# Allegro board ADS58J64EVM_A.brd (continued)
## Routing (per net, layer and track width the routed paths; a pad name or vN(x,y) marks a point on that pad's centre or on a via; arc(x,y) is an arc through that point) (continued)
VCC1_VCC5_VCC6: length 6.6
  TOP w0.305: U5.10 87.77,63.51 v3(88.27,64.01) ; v3(82.55,52.96) 82.8,52.7 v3(83.54,52.7) v3(84.58,52.7) 84.77,52.89 U5.33 ; U5.36 86.27,53.11 ; 86.27,53.11 86.27,52.62 86.28,52.62 ; 86.27,53.11 v3(86.28,53.11) 86.28,52.62 ; 86.28,52.62 86.28,52.6 v3(86.49,52.4)
  vias: v3(77.34,51.94) v3(77.34,50.85) v3(78.36,51.94) v3(78.36,50.85) v3(79.38,51.94) v3(79.63,50.42) v3(80.19,51.41) v3(80.77,50.42) v3(81.15,51.94) v3(81.91,50.8) v3(83.57,51.69)
VCC2_CG1: length 0.6
  TOP w0.305: U5.17 v3(83.94,62.75)
  vias: v3(80.26,62.87) v3(81.15,62.87) v3(82.8,62.48) v3(83.31,62.99)
VCC3_SYSREF: length 5.4
  TOP w0.305: U5.21 v3(80.29,60.17)
  BOTTOM w0.254: C173.1 FB6.2
VCC4_CG2: length 7.3
  TOP w0.305: v3(78.49,57.53) v3(79.38,57.53) 79.51,57.67 v3(80.4,57.67) 80.41,57.66 v3(81.53,57.66) v3(83.06,57.66) 83.93,57.66 U5.26
  BOTTOM w0.254: C102.1 v3(79.38,57.53) v3(78.49,57.53)
VCC7_OSCOUT: length 3.2
  TOP w0.254: U5.39 v3(87.77,52.84)
  BOTTOM w0.254: v3(87.77,52.84) 87.77,51.57 87.76,51.56 FB3.2
VCC8_OSCIN: length 4.9
  TOP w0.305: U5.42 89.27,51.68 89.03,51.44 v3(89.03,50.93) v3(89.03,50.29)
  BOTTOM w0.254: FB11.2 89.28,50.67 v3(89.03,50.93)
VCC8_VCC10: length 3.9
  TOP w0.305: v3(94.67,52.17) v3(94.06,52.17) v3(93.45,52.17) 92.96,52.17 91.77,53.36 U5.47
  vias: v3(87.2,48.13) v3(87.2,47.19) v3(88.27,47.24) v3(88.29,48.16) v3(89.38,48.16) v3(89.41,47.17) v3(92.48,47.24) v3(93.09,48.06) v3(93.62,47.24) v3(96.01,52.45) v3(96.9,51.82) v3(97.79,52.45) v3(97.79,51.05) v3(99.82,51.82) v3(100.96,51.82) v3(102.11,52.32) v3(102.87,51.31)
VCC9_CP2: length 4.6
  TOP w0.305: U5.45 90.77,52.51 v3(90.8,52.48) 90.93,52.48 v3(91.41,51.99) v3(92.02,51.38) v3(92.58,50.83) v1(93.09,50.32)
  BOTTOM w0.254: C164.1 v3(90.8,52.48)
VCC11_CG3: length 0.9
  TOP w0.305: U5.53 v3(93.95,56.67)
  vias: v3(94.23,55.25) v3(95.05,56.39) v3(95.4,55.27) v3(96.65,55.25) v3(97.66,55.75) v3(98.93,56.26) v3(99.69,55.25)
VCC12_CG0: length 8.5
  TOP w0.305: C100.1 94.74,62.76 94.16,62.76 94.16,62.3 ; C100.1 94.84,62.3 ; C100.1 v3(94.82,62.66) ; U5.64 93.7,62.17 ; 93.7,62.17 93.7,62.3 94.16,62.3 ; 93.7,62.17 93.95,62.17 ; 94.16,62.3 93.95,62.3 93.95,62.17 ; 94.16,62.3 94.16,62.17 ; 94.16,62.3 94.16,62.4 94.48,62.3 94.84,62.3 ; 93.95,62.17 94.16,62.17 ; 94.16,62.17 94.33,62.17 ; 94.33,62.17 94.33,62.57 94.42,62.57 ; 94.33,62.17 95.05,62.17 95.05,62.3 ; 94.84,62.3 95.05,62.3 ; 95.05,62.3 95.18,62.3 v3(95.53,62.65) ; v3(94.82,62.66) 94.73,62.57 94.42,62.57 ; v3(94.82,62.66) 94.42,62.66 94.42,62.57
  TOP w0.508: C100.1 95.52,62.66 v3(95.53,62.65)
  vias: v3(93.37,62.28) v3(94.18,62.31)
AAINM: length 1.3
  TOP w0.508: T2.1 T1.3
AAINP: length 1.3
  TOP w0.508: T2.3 T1.1
ACLK_N: length 4.3
  TOP w0.241: C193.2 111.71,90.55 111.71,88.54 111.58,88.42 R34.2 111.58,88.11 111.7,88 111.7,86.92 111.64,86.86 U1.28
  vias: v1(111.61,90.68)
ACLK_P: length 4.3
  TOP w0.241: v1(112.22,90.68) 112.09,90.55 112.09,88.52 112.19,88.42 R34.1 112.19,88.11 112.08,88 112.08,86.92 112.14,86.86 U1.27
ACLKN: length 11.9
  BOTTOM w0.241: T5.3 111.46,101.85 111.72,101.59 111.72,91.86 111.61,91.74 R39.1
ACLKP: length 11.9
  BOTTOM w0.241: R35.1 112.22,91.74 112.1,91.86 112.1,101.64 112.32,101.85 T5.4
ADC_CLK: length 3.4
  BOTTOM w0.508: J6.1 C43.1
ADC_SCLK: length 90.2
  TOP w0.127: v1(47.88,55.63) 47.89,55.64 U3.33 ; v1(117.42,79.91) U1.6
  L6-PWR2 w0.127: v1(47.88,55.63) 47.98,55.52 50.24,55.52 50.44,55.73 58.27,55.73 J25.1 59.66,60.76 64.06,65.15 74.24,65.15 75.53,66.43 90.64,66.43 91.54,67.34 106.27,67.34 106.65,67.72 109.4,67.72 111.84,70.15 v1(113.28,70.15)
  BOTTOM w0.127: v1(117.42,79.91) 114.33,79.91 113.6,79.18 113.6,77.38 113.16,76.94 113.16,70.28 v1(113.28,70.15)
ADC_SDIO: length 101.3
  TOP w0.127: U3.35 46.89,54.46 v1(46.91,54.43) ; U1.5 118.45,79.41 119.02,78.83 v1(119.02,78.82)
  L6-PWR2 w0.127: v1(112.57,64.74) 102.34,64.74 101.78,64.19 91.82,64.19 91.05,63.41 76.77,63.41 76.26,63.92 75.04,63.92 74.63,63.5 64.82,63.5 62,60.68 62,53.09 60.96,52.04 J25.3 57.51,54.2 47.14,54.2 v1(46.91,54.43)
  BOTTOM w0.127: v1(112.57,64.74) 114.62,66.79 114.62,77.01 114.96,77.35 117.56,77.35 v1(119.02,78.82)
ADC_SDO: length 104.5
  TOP w0.127: U3.36 46.39,53.93 v1(46.3,53.85)
  L6-PWR2 w0.127: v1(46.3,53.85) 46.48,53.67 55.5,53.67 J25.4 61.11,49.5 62.99,51.38 62.99,60.3 64.49,61.8 84.51,61.8 84.96,62.26 92.18,62.26 92.81,61.62 95.43,61.62 96.42,62.61 105.13,62.61 106.68,64.16 109.09,64.16 109.78,63.47 v1(110.59,63.47)
  BOTTOM w0.127: v2(116.79,82.41) 115.96,82.41 112.66,79.11 112.64,68.5 112.17,68.02 112.17,66.24 111.25,65.33 111.25,64.14 v1(110.59,63.47)
ADC_SEN: length 98.4
  TOP w0.127: v1(118.72,80.04) 118.34,80.41 U1.7 ; U3.34 47.39,55.02 v1(47.42,54.99)
  L6-PWR2 w0.127: v1(113.41,67.03) 110.9,67.03 110.26,66.4 104.34,66.4 103.5,65.56 100.33,65.56 99.42,64.64 91.69,64.64 90.42,65.91 75.92,65.91 74.6,64.59 64.21,64.59 60.99,61.37 60.99,56.08 59.66,54.76 J25.2 59.56,54.69 47.73,54.69 v1(47.42,54.99)
  BOTTOM w0.127: v1(113.41,67.03) 114.21,67.83 114.21,77.05 114,77.27 114,79.09 114.41,79.5 118.19,79.5 v1(118.72,80.04)
ADCCLK: length 3.6
  BOTTOM w0.508: C43.2 111.89,104.9 112.39,104.39 T5.6
AIN+: length 16.5
  TOP w0.508: J1.1 76.8,93.85 76.8,87.33 arc(76.97,86.49) 77.44,85.78 arc(78.1,85.33) 78.89,85.18 T1.4
AINM: length 8.6
  TOP w0.241: R6.2 R63.1 100.14,83.85 106.46,83.85 106.52,83.91 U1.41
AINP: length 8.6
  TOP w0.241: R2.2 R101.2 100.14,83.47 106.47,83.47 106.53,83.41 U1.42
BBINM: length 1.3
  TOP w0.508: T7.1 T6.3
BBINP: length 1.3
  TOP w0.508: T7.3 T6.1
BIN: length 16.5
  TOP w0.508: T6.4 93.2,102.38 92.63,102.95 arc(92.36,103.35) 92.27,103.83 arc(92.34,104.21) 92.56,104.53 92.57,104.53 arc(93.03,104.84) 93.58,104.95 96,104.95 arc(96.87,105.31) 97.23,106.18 97.23,106.55 arc(96.87,107.41) 96.01,107.77 94.22,107.77 arc(93.93,107.83) 93.69,107.99 arc(93.4,108.42) 93.3,108.93 93.3,111.63 J17.1
BINM: length 8.6
  TOP w0.241: U1.37 106.99,86.23 102.38,90.84 R146.2 R142.2
BINP: length 8.7
  TOP w0.241: R141.2 R145.1 102.61,91.14 107.19,86.56 U1.36
CCINM: length 1.3
  TOP w0.508: T8.1 T9.3
CCINP: length 1.3
  TOP w0.508: T8.3 T9.1
CIN: length 16.5
  TOP w0.508: T8.4 134,101.76 arc(134.27,102.17) 134.37,102.65 134.37,102.65 arc(134.2,103.49) 133.72,104.21 arc(133.21,104.55) 132.6,104.67 130.23,104.67 arc(129.79,104.76) 129.42,105.01 arc(129.02,105.61) 128.88,106.32 arc(129.01,106.96) 129.37,107.5 129.63,107.76 arc(130.25,108.69) 130.47,109.78 J18.1
CINM: length 8.6
  TOP w0.241: U1.18 116.79,86.33 121.44,90.98 121.88,90.98 R157.1 R153.2
CINP: length 8.6
  TOP w0.241: R154.2 R158.2 121.03,91.11 116.48,86.56 U1.19
CLK_IN: length 5.8
  TOP w0.483: C122.1 v3(84.84,49.15)
  TOP w0.508: R62.2 v3(84.84,49.15)
CLK_LAO_0M: length 82.6
  TOP w0.241: C86.1 103.56,59 106.01,59 106.47,58.55 106.47,58.07 106.78,57.76 107.26,57.76 110.01,55.01 110.01,52.73 110.69,52.04 112.97,52.04 117.81,47.21 117.81,44.2 118.54,43.46 121.56,43.46 127.97,37.05 127.97,33.81 128.73,33.05 132.31,33.05 132.8,32.56 132.8,30.38 133.26,29.91 135.41,29.91 135.73,29.6 135.73,27.45 136.19,26.98 138.03,26.98 139.34,25.68 139.76,25.68 v3(140.06,25.39)
  BOTTOM w0.152: 155.89,20.83 155.89,20.79 155.96,20.73 155.96,16.54 155.8,16.38 J3.G7
  BOTTOM w0.241: v3(140.06,25.39) 140.35,25.68 151.98,25.68 152.46,25.2 152.46,24.63 152.69,24.4 153.26,24.4 155.89,21.77 155.89,20.83
CLK_LAO_0P: length 82.6
  TOP w0.241: C89.1 103.5,59.39 106.17,59.39 110.39,55.17 110.39,52.89 110.85,52.43 113.13,52.43 118.19,47.37 118.19,44.35 118.7,43.84 121.72,43.84 128.35,37.21 128.35,33.97 128.89,33.43 132.47,33.43 133.18,32.71 133.18,30.53 133.42,30.29 135.57,30.29 136.11,29.76 136.11,27.61 136.35,27.36 138.19,27.36 139.5,26.06 139.76,26.06 v3(140.06,26.35)
  BOTTOM w0.152: 156.27,20.83 156.27,20.79 156.21,20.73 156.21,16.54 156.36,16.38 156.72,16.38
  BOTTOM w0.241: v3(140.06,26.35) 140.35,26.06 152.14,26.06 156.27,21.93 156.27,20.83
CLK_N: length 6.8
  TOP w0.241: 84.35,64.32 84.39,64.32 84.77,63.95 U5.16
  TOP w0.254: 84.35,64.32 83.25,64.32 82.67,64.9 82.67,66.06 82.3,66.43 R40.1 82.25,66.98 82.25,67.51 82.3,67.56 C71.1
CLK_P: length 6.8
  TOP w0.241: U5.15 85.27,63.76 85.15,63.87 85.15,64.11 84.55,64.7 84.53,64.7 84.52,64.72 84.35,64.72
  TOP w0.254: 84.35,64.72 83.41,64.72 83.06,65.07 83.06,66.06 83.44,66.43 R21.1 C70.1
CLKIN: length 5.1
  TOP w0.508: R62.1 J12.1
CLKIN1N: length 3.8
  TOP w0.229: C175.2 C79.2
  TOP w0.241: C79.2 86.11,51.81 85.77,52.15 U5.35
CLKIN1P: length 2.7
  TOP w0.241: U5.34 85.27,52.24 84.84,51.81 C122.2
CLKLA_0N: length 13.4
  TOP w0.241: U5.63 93.97,61.67 94.02,61.61 94.65,61.61 95.19,61.08 95.19,60.04 95.76,59.46 96.6,59.46 97.01,59.87 97.01,60.72 97.47,61.19 98.99,61.19 99.46,60.72 99.46,59.6 99.7,59.36 100.74,59.36 R80.1 101.12,59.74 C89.2
CLKLA_0P: length 13.4
  TOP w0.241: C86.2 101.12,58.6 R79.1 100.74,58.98 99.54,58.98 99.08,59.44 99.08,60.57 98.84,60.81 97.63,60.81 97.39,60.57 97.39,59.71 96.76,59.08 95.61,59.08 94.81,59.88 94.81,60.92 94.5,61.23 94.02,61.23 93.97,61.17 U5.62
CLKM: length 52.1
  TOP w0.241: C48.2 111.61,91.74 111.72,91.86 111.72,93.33 110.53,94.52 110.23,94.52 110.14,94.43 109.84,94.43 109.63,94.64 109.63,94.94 109.72,95.03 109.72,95.33 109.35,95.71 108.62,95.71 v3(108.33,95.42)
  BOTTOM w0.241: v3(83.44,69.09) 83.06,69.47 83.06,82.21 83.47,82.63 84.05,82.63 84.27,82.85 84.27,83.43 96.58,95.73 97.15,95.73 97.48,95.4 97.87,95.4 98.2,95.73 108.01,95.73 v3(108.33,95.42)
CLKP: length 52.1
  TOP w0.241: v3(108.33,96.38) 108.62,96.09 109.5,96.09 112.1,93.49 112.1,91.86 112.22,91.74 C47.2
  BOTTOM w0.241: v3(82.3,69.09) 82.68,69.47 82.68,82.37 96.42,96.11 108.06,96.11 v3(108.33,96.38)
CP1: length 43.4
  TOP w0.254: v3(82.4,47.22) 82.4,52.12 81.28,53.24 C65.1 C60.1 81.74,54.61 81.79,54.67 U5.32
  BOTTOM w0.254: v3(82.4,47.22) 82.4,47.19 83.54,46.05 103.68,46.05 C94.2
  vias: v3(111.47,38.12)
CP2: length 5.3
  TOP w0.152: U5.46 91.27,53.13 93.09,51.31 C69.1 C66.1
DA_M: length 1.7
  TOP w0.241: C28.1 109.58,75.18 109.58,76.04 109.64,76.1 U1.59
DA_P: length 1.7
  TOP w0.241: U1.58 109.14,76.1 109.2,76.04 109.2,75.26 C27.1
DAM: length 87
  TOP w0.241: v1(150.37,8.76) 150.81,8.32 150.81,7.91 150.57,7.67 149.76,7.67 149.3,8.13 149.3,9.08 149.51,9.29 149.97,9.29 150.19,9.5 150.19,9.8 149.97,10.01 149.51,10.01 149.3,10.23 149.3,29.83 109.56,69.56 109.56,73.93 109.65,74.02 C28.2
DAP: length 87
  TOP w0.241: C27.2 109.04,74.07 109.18,73.93 109.18,69.41 148.92,29.67 148.92,7.98 149.61,7.29 150.73,7.29 151.19,7.75 151.19,8.32 v1(151.64,8.76)
DB_M: length 1.7
  TOP w0.241: U1.62 111.14,76.1 111.08,76.04 111.08,75.21 C30.1
DB_P: length 1.7
  TOP w0.241: U1.61 110.64,76.1 110.7,76.04 110.7,75.24 C29.1
DBM: length 88.8
  TOP w0.241: v1(155.45,8.76) 155.89,8.32 155.89,7.98 155.6,7.69 154.24,7.69 154.02,7.91 154.02,8.21 154.34,8.53 154.34,8.83 154.13,9.05 153.83,9.05 153.51,8.72 153.21,8.72 151.84,10.09 151.84,30.43 111.06,71.21 111.06,73.93 111.18,74.04 C30.2
DBP: length 88.7
  TOP w0.241: v1(156.72,8.76) 156.27,8.32 156.27,7.82 155.76,7.31 154.09,7.31 151.46,9.93 151.46,30.28 110.68,71.06 110.68,73.93 110.57,74.04 C29.2
DC_M: length 1.7
  TOP w0.241: C32.1 112.7,75.23 112.7,76.04 112.64,76.1 U1.65
DC_P: length 1.7
  TOP w0.241: U1.66 113.14,76.1 113.08,76.04 113.08,75.21 C31.1
DCM: length 89.2
  TOP w0.241: C32.2 112.57,74.04 112.69,73.93 112.69,71.92 154.05,30.56 154.05,11.07 155.27,9.86 160.73,9.86 160.97,9.61 160.97,9.21 v3(160.53,8.76)
DCP: length 89.2
  TOP w0.241: C31.2 113.18,74.04 113.07,73.93 113.07,72.08 154.43,30.71 154.43,11.23 155.43,10.24 160.89,10.24 161.35,9.77 161.35,9.21 v1(161.8,8.76)
DD_M: length 1.7
  TOP w0.241: C34.1 114.2,75.21 114.2,76.04 114.14,76.1 U1.68
DD_P: length 1.7
  TOP w0.241: C33.1 114.58,75.24 114.58,76.04 114.64,76.1 U1.69
DDINM: length 1.3
  TOP w0.508: T4.3 T3.1
DDINP: length 1.3
  TOP w0.508: T4.1 T3.3
DDM: length 81.2
  TOP w0.241: v3(155.45,11.3) 155.89,11.75 155.89,13.73 156.51,14.35 156.51,30.88 114.21,73.18 114.21,73.93 114.1,74.04 C34.2
DDP: length 81.2
  TOP w0.241: C33.2 114.71,74.04 114.59,73.93 114.59,73.34 156.9,31.04 156.9,14.19 156.27,13.57 156.27,11.75 v3(156.72,11.3)
DIN: length 16.5
  TOP w0.508: J5.1 146.98,89.77 arc(146.73,88.53) 146.03,87.48 141.55,83 arc(140.6,82.37) 139.47,82.14 T3.4
DINM: length 8.6
  TOP w0.241: U1.14 117.23,83.91 117.29,83.85 123.63,83.85 R119.2 R8.2
DINP: length 8.6
  TOP w0.241: R12.2 R107.1 123.63,83.47 117.3,83.47 117.24,83.41 U1.13
DRVDD1.15V: length 4.3
  TOP w0.241: v2(117.4,80.91) v2(116.79,80.91) ; v2(107.01,80.91) U1.47 106.74,80.91 106.2,80.37 v1(105.89,80.37)
  TOP w0.254: v1(117.98,80.92) 117.97,80.91 v2(117.4,80.91)
  BOTTOM w0.254: v1(117.98,80.92) 117.41,80.92 v2(117.4,80.91) v2(116.79,80.91) ; v2(106.39,80.55) 106.2,80.37 v1(105.89,80.37)
  vias: v1(40.01,85.52) v1(40.01,84.23) v1(40.11,88.62) v1(40.08,87.6) v1(40.08,86.64) v1(41.17,87.6) v1(41.17,86.64) v1(41.1,85.52) v1(41.1,84.23) v1(41.2,88.62) v1(42.37,88.6) v1(42.34,87.58) v1(42.34,86.61) v1(43.76,88.6) v1(43.74,87.58) v1(43.74,86.61) v1(44.3,85.39) v1(44.32,84.1) v1(45.16,88.62) v1(45.14,87.6) v1(45.14,86.64) v1(45.39,85.39) v1(45.42,84.1)
FMC_CLK_N: length 80.5
  BOTTOM w0.241: v1(110.97,90.68) 110.97,90.62 111.71,89.88 111.71,89.26 112.19,88.77 116.9,88.77 124.08,81.59 124.08,79.95 127.95,76.08 127.95,20.64 127.51,20.19
FMC_CLK_P: length 80.5
  BOTTOM w0.241: 128.78,20.19 128.33,20.64 128.33,76.24 124.46,80.11 124.46,81.75 117.06,89.15 112.35,89.15 112.09,89.41 112.09,89.86 112.85,90.62 v1(112.85,90.68)
FMC_D5: length 106.9
  TOP w0.127: U3.7 v1(54.4,47.47)
  L6-PWR2 w0.127: v1(54.4,47.47) 56.31,47.47 57.24,46.55 74.89,46.55 76.07,45.36 88.9,45.36 89.5,44.77 92.27,44.77 92.69,45.19 99.09,45.19 100.22,44.06 115.89,44.06 119.23,40.72 119.23,39.42 121.82,36.83 121.82,36.26 124.87,33.21 125.44,33.21 125.9,32.75 125.9,32.25 126.61,31.53 127.15,31.53 127.39,31.29 127.39,30.57 128.94,29.02 129.4,29.02 131.72,26.69 131.72,26.38 137.3,20.8 137.62,20.8 139.5,18.92 139.5,18.23 141.81,15.92 143.56,15.92 v1(144.02,16.38)
FMC_D6: length 106.7
  TOP w0.127: U3.8 v1(54.83,47.97)
  L6-PWR2 w0.127: v1(144.02,17.65) 144.02,17.55 143.52,17.05 141.47,17.05 140.32,18.19 140.32,18.59 136.77,22.14 136.77,23.07 136.27,23.57 135.99,23.57 127.72,31.84 126.91,31.84 126.2,32.55 126.2,32.96 125.64,33.52 125.33,33.52 125.08,33.76 125.08,34.3 123.42,35.97 123.26,35.97 119.76,39.46 119.76,41.03 118.52,42.27 118.52,42.97 117.04,44.44 116.64,44.44 115.24,45.85 76.4,45.85 75.11,47.14 57.49,47.14 56.67,47.97 v1(54.83,47.97)
FMC_DIR_CONTROL: length 105.5
  TOP w0.127: U3.15 v1(54.59,51.47)
  L6-PWR2 w0.127: v1(54.59,51.47) 54.78,51.47 58.52,47.73 75.26,47.73 76.66,46.33 116.2,46.33 120.76,41.77 120.76,40.64 120.65,40.52 120.65,39.99 125.06,35.58 125.06,35.13 128.71,31.48 129.46,31.48 129.71,31.24 129.71,30.7 v1(142.75,17.65)
FMC_SCLK: length 109.4
  TOP w0.127: U3.2 v1(54.98,44.97)
  L6-PWR2 w0.127: v1(54.98,44.97) 58.12,41.83 70.38,41.83 73,39.22 83.7,39.22 84.32,39.83 85.36,39.83 85.97,39.22 100.33,39.22 100.96,38.58 114.49,38.58 122.98,30.1 123.49,30.1 124,29.59 124,29.43 131.13,22.3 131.46,22.3 133.17,20.59 134.02,20.59 134.25,20.36 134.25,19.19 134.96,18.48 135.28,18.48 142.04,11.72 142.04,11.25 142.52,10.77 146.02,10.77 v1(146.56,11.3)
FMC_SDIO: length 107.4
  TOP w0.127: U3.3 v1(54.39,45.47)
  L6-PWR2 w0.127: v1(145.29,11.3) 145.12,11.47 143.15,11.47 134.92,19.69 134.92,20.12 133.8,21.25 133.37,21.25 130.67,23.95 130.1,23.95 126.56,27.49 126.56,27.72 123.75,30.53 123.33,30.53 122.28,31.59 122.28,32.11 118.08,36.31 117.5,36.31 114.09,39.73 91.64,39.73 88.48,42.89 85.41,42.89 84.96,42.44 58.22,42.44 55.19,45.47 v1(54.39,45.47)
FMC_SDO: length 108.9
  TOP w0.127: U3.4 v1(55.09,45.97)
  L6-PWR2 w0.127: v1(55.09,45.97) 55.42,45.97 58.47,42.93 84.68,42.93 85.09,43.33 88.72,43.33 89.38,42.67 94.26,42.67 95.55,41.38 113.79,41.38 120.82,34.35 121.38,34.35 121.63,34.11 121.63,33.61 125.3,29.93 125.68,29.93 125.92,29.69 125.92,29.3 126.87,28.35 127.23,28.35 129.65,25.92 129.65,25.91 132.88,22.69 132.88,22.66 133.3,22.24 133.34,22.24 137.36,18.21 137.67,18.21 138.15,17.73 138.15,17.25 143.36,12.04 145.97,12.04 146.51,12.57 v1(146.56,12.57)
FMC_SEN_ADC: length 107.9
  TOP w0.127: U3.5 v1(54.39,46.47)
  L6-PWR2 w0.127: v1(145.29,12.57) 144.89,12.97 143.07,12.97 140.59,15.45 140.59,15.77 133.82,22.54 133.43,22.54 133.18,22.79 133.18,23.18 130.49,25.87 130.49,26.26 130.25,26.5 129.71,26.5 127.11,29.1 126.83,29.1 126.58,29.34 126.58,29.78 125.66,30.7 125.3,30.7 125.06,30.94 125.06,31.51 123.47,33.1 122.86,33.1 122.17,33.79 122.17,34.19 121.45,34.91 121.01,34.91 113.99,41.94 95.76,41.94 94.54,43.15 89.48,43.15 88.7,43.94 83.11,43.94 82.85,43.69 58.43,43.69 55.65,46.47 v1(54.39,46.47)
FMC_SEN_LMK: length 106.8
  TOP w0.127: U3.6 v1(55.01,46.97)
  L6-PWR2 w0.127: v1(55.01,46.97) 56.03,46.97 56.98,46.02 74.55,46.02 76.16,44.41 77.18,44.41 77.74,44.97 88.47,44.97 89.65,43.79 94.79,43.79 96.06,42.52 114.78,42.52 122.95,34.35 122.95,33.76 123.19,33.52 123.79,33.52 129.01,28.29 129.4,28.29 131.3,26.4 131.3,25.79 133.71,23.38 133.78,23.38 134.02,23.14 134.02,23.06 141.57,15.52 144.42,15.52 v1(145.29,16.38)
FMC_SYSREF_N: length 80.5
  BOTTOM w0.241: 116.08,20.19 116.29,20.19 116.54,20.43 116.54,23.5 117.76,24.72 117.76,25.99 118.7,26.93 119.97,26.93 122.15,29.11 122.15,42.9 109.24,55.8 109.24,77.02 109.72,77.5 109.72,84.9 108.62,85.99 108.62,90.41 108.38,90.65 v1(107.87,90.65)
FMC_SYSREF_P: length 80.5
  BOTTOM w0.241: 117.35,20.19 117.12,20.19 116.92,20.4 116.92,23.34 118.14,24.56 118.14,25.83 118.86,26.55 120.13,26.55 122.53,28.95 122.53,43.05 109.62,55.96 109.62,76.86 110.1,77.35 110.1,85.05 109,86.15 109,90.41 109.25,90.65 v1(109.75,90.65)
FPGA_JESD_CLKM: length 82.6
  TOP w0.241: C67.2 104.01,62.48 105.86,62.48 140.79,27.56 141.38,27.56 141.38,27.55 v3(141.66,27.27)
  BOTTOM w0.152: 158.43,20.83 158.43,20.79 158.5,20.73 158.5,12.73 158.34,12.57 157.99,12.57
  BOTTOM w0.241: 158.43,20.83 158.13,21.13 158.13,21.47 158.43,21.77 158.43,22.16 154.27,26.31 153.62,26.31 153.32,26.61 153.32,26.96 153.32,26.97 153.32,27.27 153.03,27.56 141.95,27.56 v3(141.66,27.27)
FPGA_JESD_CLKP: length 82.6
  TOP w0.241: C68.2 104.01,62.87 106.02,62.87 140.94,27.94 141.38,27.94 141.38,27.95 v3(141.66,28.23)
  BOTTOM w0.152: 158.81,20.83 158.81,20.79 158.75,20.73 158.75,12.73 158.9,12.57 159.26,12.57
  BOTTOM w0.241: v3(141.66,28.23) 141.95,27.94 153.19,27.94 158.81,22.31 158.81,20.83
FPGA_JESD_SYSREFM: length 82.6
  TOP w0.241: 100.33,66.8 100.71,67.18 104.44,67.18 104.72,66.9 104.72,66.68 104.97,66.43 105.19,66.43 105.49,66.14 105.49,65.22 106.66,64.05 106.66,63.99 106.87,63.78 107.17,63.78 107.38,63.99 107.38,64.05 107.59,64.26 108.05,64.26 109.22,63.09 109.22,62.03 111.08,60.17 112.14,60.17 113.56,58.75 113.56,57.97 115.04,56.49 115.77,56.49 116.45,55.81 116.45,54.72 117.71,53.46 118.57,53.46 119.7,52.33 119.7,51.62 121.06,50.26 121.52,50.26 142.88,28.91 142.88,24.51 143.46,23.93 144.03,23.93 v3(144.35,23.61)
  BOTTOM w0.152: J3.G10 151.99,16.38 152.15,16.54 152.15,20.73 152.08,20.79 152.08,20.83
  BOTTOM w0.241: v3(144.35,23.61) 144.67,23.93 149.8,23.93 152.08,21.64 152.08,20.83
FPGA_JESD_SYSREFP: length 82.6
  TOP w0.241: 100.33,67.94 100.71,67.56 104.6,67.56 105.87,66.3 105.87,65.38 106.6,64.64 108.2,64.64 109.6,63.25 109.6,62.19 111.24,60.55 112.29,60.55 113.94,58.91 113.94,58.13 115.2,56.87 115.93,56.87 116.83,55.97 116.83,54.88 117.87,53.84 118.73,53.84 120.08,52.49 120.08,51.78 121.22,50.64 121.68,50.64 143.26,29.06 143.26,24.67 143.62,24.31 144.08,24.31 v3(144.35,24.57)
  BOTTOM w0.152: 152.46,20.83 152.46,20.79 152.4,20.73 152.4,16.54 152.55,16.38 J3.G9
  BOTTOM w0.241: v3(144.35,24.57) 144.61,24.31 149.95,24.31 152.46,21.8 152.46,20.83
FTDI_D5: length 12.1
  TOP w0.127: U3.54 35.72,54.97 v1(35.69,54.94)
  BOTTOM w0.127: U7.9 32.02,47.44 35.69,51.1 v1(35.69,54.94)
FTDI_D6: length 15.9
  TOP w0.127: v1(29.4,46.82) 29.18,47.04 29.18,50.55 34.11,55.47 U3.53
  BOTTOM w0.127: v1(29.4,46.82) 30.92,46.82 U7.10
FTDI_DIR_CONTROL: length 11.7
  TOP w0.127: v1(35.23,55.98) 37.68,55.98 U3.52
  BOTTOM w0.127: U7.6 32.52,49.39 35.23,52.1 v1(35.23,55.98)
FTDI_SCLK: length 7.2
  TOP w0.127: U3.61 33.32,51.47 v1(32.13,52.65)
  BOTTOM w0.127: v1(32.13,52.65) 32.11,52.64 U7.1
FTDI_SDIO: length 7.9
  TOP w0.127: U3.58 35.16,52.97 v1(34.82,52.63)
  BOTTOM w0.127: v1(34.82,52.63) 32.23,50.04 U7.5
FTDI_SDO: length 7.6
  TOP w0.127: U3.57 34.78,53.47 v1(33.93,52.63)
  BOTTOM w0.127: U7.3 32.67,51.34 33.8,52.47 v1(33.93,52.63)
FTDI_SEN_ADC: length 12
  TOP w0.127: U3.56 v1(36.25,53.97)
  BOTTOM w0.127: v1(36.25,53.97) 36.18,53.9 36.18,50.41 31.91,46.14 U7.11
FTDI_SEN_LMK: length 7.8
  TOP w0.127: U3.55 34.89,54.47 v1(33.05,52.63)
  BOTTOM w0.127: U7.2 32.4,51.99 v1(33.05,52.63)
IOVDD1.15V: length 7.8
  TOP w0.241: v2(112.14,76.76) 112.14,75.99 v1(111.86,75.72) ; v2(116.79,78.91) v2(117.24,78.91) 117.75,78.91 v1(117.75,78.92) ; v2(115.14,76.76) 115.14,75.9 v1(115.32,75.72) ; v1(106.07,78.89) 106.09,78.91 v2(106.99,78.91)
  TOP w0.254: v1(108.43,75.64) 108.64,75.84 v2(108.64,76.76)
  L3-PWR1 w0.127: 83.62,68.62 83.9,68.9 83.9,69.07
  BOTTOM w0.254: v2(116.79,78.91) v2(117.24,78.91) 117.25,78.92 v1(117.75,78.92) ; v1(106.07,78.89) 106.97,78.89 v2(106.99,78.91)
  vias: v2(108.64,76.19) v2(112.13,76.26) v2(115.13,76.28) v3(52.93,73.58) v3(52.93,72.52) v3(52.93,71.32) v3(52.93,70.18) v3(52.98,69.19) v3(54.08,73.63) v3(54.08,72.57) v3(54.08,71.37) v3(54.08,70.23) v3(54.13,69.24) v3(55.22,73.58) v3(55.22,72.52) v3(55.22,71.32) v3(55.22,70.18) v3(55.27,69.19) v3(56.26,73.61) v3(56.26,72.54) v3(56.26,71.35) v3(56.26,70.21) v3(56.31,69.22)
JESD_CLKM: length 13.4
  TOP w0.241: U5.2 91.77,63.87 91.83,63.93 91.83,64.39 92.31,64.87 95.31,64.87 95.89,64.29 99.55,64.29 100.95,62.89 102.26,62.89 v3(102.62,63.25)
JESD_CLKP: length 13.4
  TOP w0.241: U5.1 92.27,63.87 92.21,63.93 92.21,64.23 92.47,64.49 92.82,64.49 92.96,64.35 92.96,64.16 93.11,64.02 93.31,64.02 93.45,64.16 93.45,64.35 93.59,64.49 95.15,64.49 95.73,63.91 99.39,63.91 100.79,62.51 102.21,62.51 v3(102.62,62.1)
JESD_SYSREFM: length 13.3
  TOP w0.241: U5.4 90.77,63.87 90.83,63.93 90.83,66.75 91.95,67.87 94.06,67.87 94.57,67.36 95.31,67.36 95.77,67.82 97.23,67.82 97.43,67.61 98.98,67.61 v3(99.31,67.94)
JESD_SYSREFP: length 13.3
  TOP w0.241: v3(99.31,66.8) 98.88,67.23 97.27,67.23 97.07,67.44 95.93,67.44 95.47,66.98 94.41,66.98 93.9,67.49 93.24,67.49 93.1,67.35 93.1,67.17 92.96,67.03 92.76,67.03 92.62,67.17 92.62,67.35 92.47,67.49 92.11,67.49 91.21,66.59 91.21,63.93 91.27,63.87 U5.3
LMK_CS: length 66.8
  TOP w0.127: v3(62.38,61.82) 62.53,61.98 80.77,61.98 81.08,61.67 U5.18
  TOP w0.152: v3(61.9,40.94) 61.26,40.31 40.84,40.31 40.39,40.76 U3.78
  BOTTOM w0.127: v3(62.38,61.82) 62.38,41.43 v3(61.9,40.94)
LMK_SCK: length 68.1
  TOP w0.127: U5.19 81.02,61.17 80.54,61.65 77.52,61.65 77.18,61.31 63.38,61.31 v3(63.37,61.32)
  TOP w0.152: U3.77 39.89,40.37 40.61,39.65 62.23,39.65 v3(62.66,40.08)
  BOTTOM w0.127: v3(62.66,40.08) 63.14,40.56 63.14,61.09 v3(63.37,61.32)
LMK_SDIO: length 68.7
  TOP w0.127: U5.20 79.17,60.67 79.13,60.71 R134.2 76.23,60.71 76.2,60.67 64.3,60.67 v3(64.26,60.63)
  TOP w0.152: U3.76 39.39,39.86 40.23,39.01 63.02,39.01 v3(63.4,39.4)
  BOTTOM w0.127: v3(64.26,60.63) 63.98,60.35 63.96,60.32 63.96,39.95 v3(63.4,39.4)
LMK_SDO: length 65
  TOP w0.254: v3(90.17,64.52) 90.27,64.42 U5.5
  BOTTOM w0.127: v3(90.17,64.52) 89.71,64.52 89.46,64.26 88.77,64.26 88.16,64.87 64.34,64.87 61.54,62.08 61.54,49.48 60.43,48.36 53.65,48.36 50.75,45.47 R113.2
LMK_SYNC: length 22
  TOP w0.254: U5.6 89.77,63.9 89.28,64.39 v3(89.28,64.9)
  TOP w0.508: R59.1 72.9,68.12 J10.1
  BOTTOM w0.508: v3(72.95,68.15) 75.31,65.79 88.39,65.79 v3(89.28,64.9)
Net_375:
  vias: v1(155.45,20.19)
Net_376:
  vias: v1(157.99,20.19)
Net_377:
  vias: v1(113.54,20.19)
Net_379:
  vias: v1(119.89,20.19)
Net_380:
  vias: v1(121.16,20.19)
Net_381:
  vias: v1(123.7,20.19)
Net_382:
  vias: v1(124.97,20.19)
Net_383:
  vias: v1(131.32,20.19)
Net_384:
  vias: v1(132.59,20.19)
Net_389:
  vias: v1(142.75,20.19)
Net_390:
  vias: v1(144.02,20.19)
Net_391:
  vias: v1(146.56,20.19)
Net_393:
  vias: v1(150.37,20.19)
Net_395:
  vias: v1(163.07,20.19)
Net_396:
  vias: v1(152.91,18.92)
Net_397:
  vias: v1(155.45,18.92)
Net_399:
  vias: v1(114.81,18.92)
Net_400:
  vias: v1(117.35,18.92)
Net_401:
  vias: v1(118.62,18.92)
Net_402:
  vias: v1(121.16,18.92)
Net_403:
  vias: v1(122.43,18.92)
Net_404:
  vias: v1(124.97,18.92)
Net_405:
  vias: v1(126.24,18.92)
Net_406:
  vias: v1(160.53,18.92)
Net_407:
  vias: v1(128.78,18.92)
Net_408:
  vias: v1(130.05,18.92)
Net_409:
  vias: v1(132.59,18.92)
Net_410:
  vias: v1(133.86,18.92)
Net_413:
  vias: v1(161.8,18.92)
Net_416:
  vias: v1(144.02,18.92)
Net_417:
  vias: v1(145.29,18.92)
Net_422:
  vias: v1(155.45,17.65)
Net_423:
  vias: v1(157.99,17.65)
Net_424:
  vias: v1(113.54,17.65)
Net_425:
  vias: v1(159.26,17.65)
Net_426:
  vias: v1(116.08,17.65)
Net_427:
  vias: v1(117.35,17.65)
Net_428:
  vias: v1(119.89,17.65)
Net_429:
  vias: v1(121.16,17.65)
Net_430:
  vias: v1(127.51,17.65)
Net_431:
  vias: v1(128.78,17.65)
Net_432:
  vias: v1(131.32,17.65)
Net_433:
  vias: v1(132.59,17.65)
Net_434:
  vias: v1(135.13,17.65)
Net_438:
  vias: v1(146.56,17.65)
Net_440:
  vias: v1(150.37,17.65)
Net_442:
  vias: v1(163.07,17.65)
Net_443:
  vias: v1(114.81,16.38)
Net_444:
  vias: v1(117.35,16.38)
Net_445:
  vias: v1(118.62,16.38)
Net_446:
  vias: v1(121.16,16.38)
Net_447:
  vias: v1(122.43,16.38)
Net_448:
  vias: v1(124.97,16.38)
Net_449:
  vias: v1(126.24,16.38)
Net_450:
  vias: v1(160.53,16.38)
Net_451:
  vias: v1(128.78,16.38)
Net_452:
  vias: v1(130.05,16.38)
Net_453:
  vias: v1(132.59,16.38)
Net_454:
  vias: v1(133.86,16.38)
Net_455:
  vias: v1(136.4,16.38)
Net_457:
  vias: v1(161.8,16.38)
Net_461:
  vias: v1(155.45,15.11)
Net_462:
  vias: v1(157.99,15.11)
Net_463:
  vias: v1(113.54,15.11)
Net_464:
  vias: v1(159.26,15.11)
Net_465:
  vias: v1(116.08,15.11)
Net_466:
  vias: v1(117.35,15.11)
Net_467:
  vias: v1(119.89,15.11)
Net_468:
  vias: v1(121.16,15.11)
Net_469:
  vias: v1(123.7,15.11)
Net_470:
  vias: v1(124.97,15.11)
Net_471:
  vias: v1(127.51,15.11)
Net_472:
  vias: v1(128.78,15.11)
Net_473:
  vias: v1(131.32,15.11)
Net_474:
  vias: v1(132.59,15.11)
Net_475:
  vias: v1(135.13,15.11)
Net_476:
  vias: v1(136.4,15.11)
Net_479:
  vias: v1(142.75,15.11)
Net_480:
  vias: v1(144.02,15.11)
Net_481:
  vias: v1(146.56,15.11)
Net_482:
  vias: v1(147.83,15.11)
Net_483:
  vias: v1(150.37,15.11)
Net_485:
  vias: v1(163.07,15.11)
Net_489:
  vias: v1(114.81,13.84)
Net_490:
  vias: v1(117.35,13.84)
Net_491:
  vias: v1(118.62,13.84)
Net_492:
  vias: v1(121.16,13.84)
Net_493:
  vias: v1(122.43,13.84)
Net_494:
  vias: v1(124.97,13.84)
Net_495:
  vias: v1(126.24,13.84)
Net_496:
  vias: v1(160.53,13.84)
Net_497:
  vias: v1(128.78,13.84)
Net_498:
  vias: v1(130.05,13.84)
Net_499:
  vias: v1(132.59,13.84)
Net_500:
  vias: v1(133.86,13.84)
Net_501:
  vias: v1(136.4,13.84)
Net_502:
  vias: v1(137.67,13.84)
Net_503:
  vias: v1(161.8,13.84)
Net_506:
  vias: v1(144.02,13.84)
Net_507:
  vias: v1(145.29,13.84)
Net_508:
  vias: v1(147.83,13.84)
Net_511:
  vias: v1(152.91,12.57)
Net_513:
  vias: v1(113.54,12.57)
Net_514:
  vias: v1(116.08,12.57)
Net_515:
  vias: v1(118.62,12.57)
Net_516:
  vias: v1(119.89,12.57)
Net_517:
  vias: v1(121.16,12.57)
Net_518:
  vias: v1(122.43,12.57)
Net_519:
  vias: v1(123.7,12.57)
Net_520:
  vias: v1(124.97,12.57)
Net_521:
  vias: v1(126.24,12.57)
Net_522:
  vias: v1(127.51,12.57)
Net_523:
  vias: v1(130.05,12.57)
Net_524:
  vias: v1(131.32,12.57)
Net_525:
  vias: v1(133.86,12.57)
Net_526:
  vias: v1(135.13,12.57)
Net_527:
  vias: v1(137.67,12.57)
Net_528:
  vias: v1(138.94,12.57)
Net_532:
  vias: v1(150.37,12.57)
Net_533:
  vias: v1(163.07,12.57)
Net_534:
  vias: v1(114.81,11.3)
Net_535:
  vias: v1(117.35,11.3)
Net_536:
  vias: v1(119.89,11.3)
Net_537:
  vias: v1(121.16,11.3)
Net_538:
  vias: v1(124.97,11.3)
Net_539:
  vias: v1(126.24,11.3)
Net_540:
  vias: v1(160.53,11.3)
Net_541:
  vias: v1(130.05,11.3)
Net_542:
  vias: v1(131.32,11.3)
Net_543:
  vias: v1(135.13,11.3)
Net_544:
  vias: v1(136.4,11.3)
Net_545:
  vias: v1(161.8,11.3)
Net_546:
  vias: v1(140.21,11.3)
Net_549:
  vias: v1(152.91,10.03)
Net_550:
  vias: v1(154.18,10.03)
Net_552:
  vias: v1(113.54,10.03)
Net_554:
  vias: v1(117.35,10.03)
Net_555:
  vias: v1(118.62,10.03)
Net_556:
  vias: v1(122.43,10.03)
Net_557:
  vias: v1(123.7,10.03)
Net_558:
  vias: v1(127.51,10.03)
Net_559:
  vias: v1(128.78,10.03)
Net_560:
  vias: v1(132.59,10.03)
Net_561:
  vias: v1(133.86,10.03)
Net_562:
  vias: v1(137.67,10.03)
Net_563:
  vias: v1(138.94,10.03)
Net_568:
  vias: v1(163.07,10.03)
Net_569:
  vias: v1(114.81,8.76)
Net_570:
  vias: v1(116.08,8.76)
Net_571:
  vias: v1(119.89,8.76)
Net_572:
  vias: v1(121.16,8.76)
Net_573:
  vias: v1(124.97,8.76)
Net_574:
  vias: v1(126.24,8.76)
Net_575:
  vias: v1(130.05,8.76)
Net_576:
  vias: v1(131.32,8.76)
Net_577:
  vias: v1(135.13,8.76)
Net_578:
  vias: v1(136.4,8.76)
Net_579:
  vias: v1(140.21,8.76)
Net_580:
  vias: v1(141.48,8.76)
Net_581:
  vias: v1(145.29,8.76)
Net_582:
  vias: v1(146.56,8.76)
OSCIN_N: length 13.9
  TOP w0.241: U5.44 90.27,52.97 90.21,52.91 90.21,49.9 91.19,48.93 91.19,44.85 91.4,44.63 91.53,44.63 91.74,44.42 91.74,44.12 91.53,43.91 91.4,43.91 91.19,43.7 91.19,43.21 91.6,42.8 92.45,42.8 C82.2
OSCIN_P: length 13.9
  TOP w0.241: C121.2 92.43,42.42 91.44,42.42 90.8,43.05 90.8,48.77 89.83,49.74 89.83,52.91 89.77,52.97 U5.43
PDN: length 84.9
  TOP w0.127: v1(106.1,69.62) 105.51,70.21 101.55,70.21 99.59,72.16 99.59,77.83 101.18,79.41 U1.50
  L6-PWR2 w0.127: v1(106.1,69.62) 107.69,71.21 116.21,71.21 117.09,70.33 129.74,70.33 129.95,70.13 153.31,70.13 161.87,78.69 163.4,78.69 JP7.2
RESET: length 99.6
  TOP w0.127: U1.48 106.78,80.41 106.23,79.86 100.88,79.86 99.11,78.09 99.11,72.01 101.37,69.75 105.18,69.75 v1(106.12,68.81)
  L6-PWR2 w0.127: v1(167.69,66.9) 168.4,67.61 168.4,76.07 168.05,76.43 162,76.43 154.94,69.37 119.9,69.37 119.76,69.23 116.46,69.23 114.95,70.74 109.25,70.74 108.53,70.03 107.34,70.03 v1(106.12,68.81)
SCAN_EN: length 13
  BOTTOM w0.127: v2(106.99,79.91) 100.94,79.91 99.95,78.92 R19.2 R20.1 94.67,78.92 TP20.1
SYNCBABM: length 78.7
  TOP w0.241: U1.56 108.14,76.43 107.49,75.79 107.49,68.5 145.9,30.1 145.9,23.13 146.06,22.96 v3(146.25,22.96)
  BOTTOM w0.152: 148.27,20.83 148.27,20.79 148.34,20.73 148.34,16.54 148.18,16.38 J3.G13
  BOTTOM w0.241: 148.27,20.83 148.27,21.59 147.94,21.92 146.87,21.92 146.55,22.24 146.55,22.66 v3(146.25,22.96)
SYNCBABP: length 79.4
  TOP w0.241: U1.55 107.64,76.47 107.11,75.95 107.11,68.35 145.52,29.94 145.52,22.97 146.04,22.45 146.47,22.45 146.47,22.45 v3(147.07,22.45)
  BOTTOM w0.152: 149.1,16.38 148.74,16.38 148.59,16.54 148.59,20.73 148.65,20.79 148.65,20.83
  BOTTOM w0.241: v3(147.07,22.45) 147.22,22.3 148.1,22.3 148.65,21.75 148.65,20.83
SYNCBCDM: length 58.1
  BOTTOM w0.152: 124.16,20.69 124.21,20.65 124.21,17.81 124.05,17.65 123.7,17.65
  BOTTOM w0.241: v1(116.76,72.26) 116.76,71.76 116.88,71.65 116.88,70.57 124.16,63.29 124.16,20.69
SYNCBCDP: length 58.1
  BOTTOM w0.152: 124.54,20.85 124.46,20.77 124.46,17.81 124.61,17.65 J3.H31
  BOTTOM w0.241: 124.54,20.85 124.54,63.44 117.26,70.73 117.26,71.65 117.37,71.76 v1(117.37,72.26)
SYSREF+: length 4.3
  TOP w0.241: U1.33 109.14,86.8 109.07,86.87 109.07,87.6 R133.1 109.03,87.85 109.03,90.54 C190.2
SYSREF-: length 4.3
  TOP w0.241: R31.2 108.65,90.49 108.65,87.8 R133.2 108.69,87.58 108.69,86.82 108.64,86.77 U1.34
SYSREF_N: length 6.8
  TOP w0.254: U5.14 85.77,63.89 85.82,63.94 85.82,64.61 86.74,65.53 87.76,65.53 88.11,65.89 88.11,66.57 R44.1 C72.1
SYSREF_P: length 6.8
  TOP w0.254: U5.13 86.27,63.89 86.21,63.94 86.21,64.45 86.9,65.14 87.92,65.14 88.51,65.72 88.51,66.54 88.9,66.93 C73.1
SYSREFM: length 52.1
  TOP w0.241: R31.1 108.48,91.69 108.62,91.83 108.62,92.38 108.29,92.71 107.66,92.71 107.45,92.5 107.45,92.36 107.23,92.15 106.93,92.15 106.72,92.36 106.72,92.5 106.51,92.71 105.96,92.71 v3(105.71,92.47)
  BOTTOM w0.241: v3(105.71,92.47) 105.47,92.71 99.83,92.71 99.43,92.3 99.11,92.3 98.7,92.71 97.82,92.71 89.81,84.7 89.81,84.05 89.57,83.81 89.22,83.81 89.22,83.81 88.92,83.81 88.52,83.41 88.52,76.54 89,76.06 93.88,76.06 94.64,75.3 94.64,72.43 93.88,71.67 89,71.67 88.52,71.19 88.52,69.47 v3(88.9,69.09)
SYSREFP: length 52.1
  TOP w0.241: R30.1 109.14,91.69 109,91.83 109,92.54 108.45,93.09 106.06,93.09 v3(105.71,93.43)
  BOTTOM w0.241: v3(87.76,69.09) 88.14,69.47 88.14,71.35 88.84,72.06 93.73,72.06 94.26,72.59 94.26,75.14 93.73,75.68 88.84,75.68 88.14,76.38 88.14,83.57 97.66,93.09 105.37,93.09 v3(105.71,93.43)
T2_1: length 3.7
  TOP w0.508: R2.1 98.08,81.88 97.82,82.14 R3.1 96.26,82.13 C141.2
T2_3: length 3.7
  TOP w0.508: R6.1 98.18,85.44 97.92,85.18 R5.2 C140.2
T4_1: length 3.7
  TOP w0.508: R8.1 125.7,85.44 125.95,85.18 R9.1 127.51,85.19 C158.2
T4_3: length 3.7
  TOP w0.508: C157.2 R11.2 125.85,82.14 125.6,81.88 R12.1
T7_1: length 3.7
  TOP w0.508: C274.2 97.86,93.44 R144.1 99.15,92.14 99.15,91.78 R142.1
T7_3: length 3.7
  TOP w0.508: C275.2 R143.2 101.31,94.29 101.67,94.29 R141.1
T9_1: length 3.7
  TOP w0.508: C203.2 123.63,95.69 R155.1 122.33,94.39 121.97,94.39 R154.1
T9_3: length 3.7
  TOP w0.508: C202.2 R156.2 124.48,92.24 124.48,91.88 R153.1
TCK: length 21.5
  TOP w0.127: J15.1 69.44,58.26 69.44,56.57 68.85,55.97 U3.24
  BOTTOM w0.152: J15.1 R57.1
TDI: length 19.9
  TOP w0.127: U3.23 53.13,55.51 64.67,55.51 v3(64.94,55.24)
  BOTTOM w0.127: R110.1 66.75,50.55 64.94,52.35 v3(64.94,55.24)
  BOTTOM w0.152: J15.9 R110.1
TDO: length 16.4
  TOP w0.127: U3.25 56.62,56.47 58.55,58.39 66.77,58.39 J15.3
TMS: length 17.5
  TOP w0.127: J15.5 66.9,54.51 65.81,53.42 58.34,53.42 56.79,54.97 U3.22
  BOTTOM w0.152: J15.5 R111.1
TRDYAB: length 4.9
  TOP w0.152: U1.54 106.82,77.41 106.38,76.96 106.38,76.35 104.55,74.52 J21.1
TRDYCD: length 5.4
  TOP w0.152: U1.1 116.95,77.41 117.32,77.04 117.32,76.35 J22.1
TRIGAB: length 5.8
  TOP w0.152: U1.53 103.9,77.91 J23.1
  BOTTOM w0.127: J23.1 104.06,78.08 R170.1
TRIGCD: length 6
  TOP w0.127: R173.1 J24.1
  TOP w0.152: U1.2 117.06,77.91 118.29,76.68 J24.1
VCPLD1.8V: length 118.5
  TOP w0.305: U3.31 48.89,57.15 49.12,56.92 v1(49.12,56.59) ; v1(42.19,56.52) 41.89,56.81 U3.45 ; U3.9 51.75,48.47 v1(51.56,48.29) ; U3.63 39.19,50.47 v1(39.24,50.42) ; U3.13 v1(51.69,50.47)
  TOP w0.508: v1(49.12,56.59) v1(49.12,56.01)
  L6-PWR2 w0.508: J15.4 70.96,56.74 72.36,56.74 74.09,55.02 77.88,55.02 78.21,55.35 84.12,55.35 85.24,54.23 91.64,54.23 92.56,53.31 105.99,53.31 120.22,67.54 156.82,67.54 161.7,72.42 164.41,72.42 166.8,74.8 JP3.1
  BOTTOM w0.508: v1(39.52,49.76) 39.24,50.04 v1(39.24,50.42) ; v1(42.19,56.52) v1(42.19,55.85) ; v1(51.69,50.47) v1(51.69,51.13) ; v1(51.56,48.29) v1(50.93,48.29)
  vias: v1(47.7,63.88) v1(47.73,63.02) v1(47.73,62.05) v1(48.77,62.98) v1(48.77,62.06) v1(48.79,63.92) v1(49.81,63.88) v1(49.78,62.94) v1(49.78,62.03) v1(53.52,63.91) v1(53.49,62.99) v1(53.52,62.05) v1(65.74,54.51) v1(65.74,49.43)
VSNS: length 5.3
  TOP w0.305: 12.19,91.8 12.75,91.8 13.13,91.41 13.13,90.09 R117.1 R115.1
N16275326: length 3
  TOP w0.508: T3.2 v3(136.69,83.67) T3.5
N16275564: length 3
  TOP w0.508: T4.2 v3(132.37,83.67) T4.5
N16918679:
  vias: v1(101.83,39.12) v1(101.8,38.1) v1(102.97,39.14) v1(102.95,38.13) v1(104.06,39.14) v1(104.04,38.13) v1(105.05,38.1) v1(105.08,39.12) v1(106.27,39.12) v1(106.25,38.1) v1(107.47,39.12) v1(107.44,38.1) v1(108.71,39.12) v1(108.69,38.1)
N16918713: length 7.1
  TOP w0.483: R88.1 R78.2
  TOP w0.508: R78.2 R87.1 103,41.85 103.5,41.34 Y1.5
N16918734: length 7.1
  TOP w0.508: Y1.4 102.74,43.88 R74.1 R73.2 R71.1
N16918766: length 3.8
  TOP w1.016: JP2.1 98.7,35.18 101.85,35.18
N16918796: length 1.1
  TOP w0.508: R71.2 C80.1
N16918798: length 2.2
  TOP w0.508: C80.2 96.14,43.32 R77.1 C82.1
N16918863: length 2.3
  TOP w0.508: C92.1 R102.1 96.24,41.87 C169.2
N16918987: length 5
  TOP w0.635: Y1.2 SJP1.2
N16974113: length 2
  TOP w0.127: v1(42.55,44.45) 41.89,43.8 U3.81
N16976956: length 144.5
  TOP w0.127: U3.51 v1(39.2,56.47)
  L6-PWR2 w0.127: v1(39.2,56.47) 39.67,55.99 39.67,55.17 41.66,53.19 53.85,53.19 58.78,48.26 61.26,48.26 66.85,53.85 66.85,57.45 67.74,58.34 71.48,58.34 72.52,59.39 81.1,59.39 81.66,59.94 95.33,59.94 96.12,59.16 107.95,59.16 110.82,62.03 113.08,62.03 119.84,68.78 155.12,68.78 159.72,73.38 163.17,73.38 JP3.2
N17045898: length 1
  TOP w0.508: C169.1 R88.2
N17135362: length 1.4
  TOP w0.203: C175.1 87.25,49.78 R104.1
N17316333: length 12.6
  TOP w0.508: R61.1 94.95,39.52 91.55,39.52 87.63,43.43 R60.2
N17990226: length 1.4
  TOP w0.508: R3.2 96.27,83.66 ; 96.27,83.66 v3(95.83,83.66) ; 96.27,83.66 R5.1
N18101124:
  vias: v1(23.32,58.83) v1(24.23,58.8)
N18135910:
  vias: v1(37.67,106.58) v1(37.69,105.36) v1(38.68,106.55) v1(38.71,105.33) v1(39.73,106.58) v1(39.75,105.36) v1(40.74,106.55) v1(40.77,105.33) v1(42.06,106.91) v1(42.09,105.69)
N18153199: length 16.3
  TOP w0.241: v3(21.59,45.01) 21.27,44.69 17.15,44.69 17.01,44.55 15.2,44.55 14.78,44.96 12.03,44.96 11.61,44.53 9.65,44.53 9.44,44.74 J13.2
  BOTTOM w0.241: U7.16 21.76,44.84 v3(21.59,45.01)
N18153225: length 1.9
  BOTTOM w0.508: C91.1 U7.20
  vias: v3(14.86,42.67) v3(15.9,43.31) v3(15.93,41.81) v3(16.15,46.3) v3(16.18,45.06) v3(16.76,42.55) v3(17.63,41.81) v3(17.7,43.33)
N18153227: length 9.8
  BOTTOM w0.254: U7.17 23.8,45.58 25.64,45.58 v3(27.58,47.52) 27.58,48.12 30.15,50.69 U7.4
N18153268: length 16.3
  TOP w0.241: v3(21.59,43.99) 21.27,44.31 17.31,44.31 17.16,44.16 15.04,44.16 14.62,44.58 12.19,44.58 11.77,44.15 9.65,44.15 9.44,43.94 J13.3
  BOTTOM w0.241: v3(21.59,43.99) 21.78,44.19 U7.15
N18164060: length 3.4
  TOP w0.508: R13.2 11.15,42.44 10.45,43.14 J13.4
N18272382: length 1.8
  TOP w0.305: U2.2 34.5,88.15 C137.1
  vias: v3(35.46,88.19) v3(35.46,85.85) v3(35.48,87.02) v3(36.4,88.19) v3(36.42,87.02) v3(36.4,85.85) v3(37.34,88.16) v3(37.36,87) v3(37.34,85.83)
N18340257:
  vias: v1(30.51,61.29)
N18400299: length 2.1
  TOP w0.152: 168.4,32.89 R91.1
N18433453: length 3.2
  TOP w0.305: U8.15 R112.2 R114.1
N18433599: length 3.4
  TOP w0.305: C135.1 14.05,92.18 R52.1 13.92,92.3 12.19,92.3
N18433651: length 1.5
  TOP w0.305: C144.1 14.05,90.65 R52.2
N18433655: length 2.2
  TOP w0.305: R51.1 13.09,92.8 12.19,92.8
N18433661: length 3.5
  TOP w0.254: U8.9 11.34,94.02 12.04,94.72 13.49,94.72 C136.1
N18433720: length 2.8
  TOP w0.254: R118.1 7.32,93.42 7.75,92.99
  TOP w0.305: R118.1 7.75,93.01 7.75,92.99 7.77,92.99 8.46,92.3 U8.14
N18433762: length 5.1
  TOP w0.254: U8.10 10.84,94.73 C124.1 ; C124.1 9.84,94.72 U8.12 ; C124.1 U8.11
  vias: v3(9.12,97.74) v3(9.12,96.47) v3(9.75,95.58) v3(9.75,94.31) v3(10.13,97.74) v3(10.13,96.47) v3(10.34,93.52) v3(10.77,95.58) v3(10.77,94.56) v3(11.15,97.74) v3(11.15,96.47) v3(12.17,97.74) v3(12.17,96.47)
N18433788: length 2.5
  TOP w0.254: U8.13 8.99,94.34 8.77,94.56 C124.2
N18529139: length 35.5
  L6-PWR2 w0.127: v1(141.48,11.3) 141.48,11.23 142.42,10.29 149.5,10.29 157.51,18.29 158.04,18.29 168.4,28.65 v3(168.4,29.18)
N18529232: length 10.4
  BOTTOM w0.241: R84.1 164.08,21.13 164.08,18.67 163.63,18.22 162.36,18.22 J3.H2
N18993446: length 1.4
  TOP w0.508: 127.51,83.66 R9.2 ; 127.51,83.66 v3(127.94,83.66) ; 127.51,83.66 R11.1
N19018410:
  vias: v1(162.28,66.9)
N19072087:
  vias: v3(7.21,45.57) v3(8.07,45.54) v3(8.92,45.57)
N19596618:
  vias: v3(68.58,44.83)
N19596621:
  vias: v3(76.71,40.39)
N19596623:
  vias: v3(68.58,40.39)
N19596624: length 35.8
  TOP w0.127: U5.48 92.88,53.84 v3(93.09,54.05) ; v3(77.67,53.84) v3(72.75,53.82)
  BOTTOM w0.127: R86.2 70.15,43.69 72.49,46.02 72.49,53.57 v3(72.75,53.82) ; v3(93.09,54.05) 93.09,54.05 79.8,54.05 79.6,53.84 v3(77.67,53.84)
N19596626: length 22.9
  TOP w0.127: U5.31 v3(72.24,55.19)
  BOTTOM w0.127: v3(72.24,55.19) 72.13,55.09 72.13,46.86 R85.2
N19596640: length 2.7
  TOP w0.254: U5.12 86.77,63.91 v3(86.99,64.14)
  BOTTOM w0.254: v3(86.99,64.14) 86.31,63.45 86.31,63.2 C88.1
N19596641: length 2.8
  TOP w0.254: U5.11 87.27,63.73 87.76,64.21 v3(87.76,64.39)
  BOTTOM w0.254: v3(87.76,64.39) 87.5,64.14 C87.1
N19596650:
  vias: v3(76.73,44.83)
N19596653: length 39.1
  TOP w0.127: U5.59 93.77,59.67 v3(94.11,59.33) ; v3(82.25,58.93) v3(76.81,58.95)
  BOTTOM w0.127: R82.2 78.28,41.53 75.18,44.63 75.18,46.41 76.2,47.42 76.2,55.78 76.81,56.39 v3(76.81,58.95) ; v3(82.25,58.93) 93.7,58.93 v3(94.11,59.33)
N19596656: length 31.5
  TOP w0.127: v3(94.23,58.04) 94.23,58.39 93.46,59.17 U5.58 ; v3(77.24,55.7) 77.27,55.68 81.74,55.68 v3(82.47,56.41)
  BOTTOM w0.127: v3(82.47,56.41) 84.53,56.41 85.01,56.9 93.09,56.9 v3(94.23,58.04) ; v3(77.24,55.7) 76.71,55.17 76.71,46.43 R81.2
N19631315: length 1.3
  TOP w0.356: 13.89,75.41 13.84,75.46 U6.3
N19631466: length 2.4
  TOP w0.356: U6.14 7.34,74.81
  TOP w0.381: 7.34,74.81 C98.1
N19631491: length 1.9
  TOP w0.356: U6.8 R83.2
N19631493: length 2.4
  TOP w0.356: U6.11 7.34,76.76
  TOP w0.381: R75.2 6.33,77.37 6.93,76.76 7.34,76.76
N19631495: length 2.2
  TOP w0.356: U6.12 7.68,76.11
  TOP w0.381: R72.2 6.59,76.23 6.71,76.11 7.68,76.11
N19631505: length 1.9
  TOP w0.356: U6.10 R76.2
N19740812: length 3.8
  TOP w0.305: U2.6 29.18,88.8 28.85,89.13 28.85,90.93 C183.1
N19741196: length 1.3
  BOTTOM w0.305: R126.1 R125.2
  vias: v2(29.77,89.46) v2(30.25,89.46)
N19751506:
  vias: v1(114.05,103.12)
N19764898: length 6.4
  TOP w0.305: U2.3 v1(33.96,88.8) C137.2
  BOTTOM w0.305: v1(34.67,84.76) 33.96,85.47 v1(33.96,88.8)
N19785823: length 1.2
  TOP w0.508: C3.2 98.06,84.17 98.18,84.3 R63.2
N19785833: length 1.2
  TOP w0.508: C3.1 98.06,83.15 98.18,83.03 R101.1
N19786108: length 1.2
  TOP w0.508: R107.2 125.49,83.03 125.63,83.16 126.23,83.16 C9.2
N19786128: length 1.2
  TOP w0.508: C9.1 125.72,84.17 125.59,84.3 R119.1
N19791732: length 1.1
  TOP w0.508: C158.1 T4.4
N19791735: length 1.1
  TOP w0.508: C157.1 130.8,82.14 T4.6
N19818342: length 2
  TOP w0.305: U10.2 36.59,96.71 C129.1
  vias: v3(37.69,96.65) v3(37.69,95.48) v3(37.69,94.31) v3(38.63,96.62) v3(38.63,95.45) v3(38.63,94.28) v3(39.6,96.62) v3(39.6,95.45) v3(39.6,94.28) v3(40.54,96.6) v3(40.54,95.43) v3(40.54,94.26)
N19818462: length 3.4
  TOP w0.305: U10.6 31.24,97.36 30.99,97.61 30.99,99.87 C134.1
N19818472: length 1.3
  BOTTOM w0.305: R161.2 31.88,98.02 v2(31.65,98.02) R162.1
  vias: v2(32.16,98.02)
N19818541: length 5.3
  TOP w0.305: C129.2 36.05,97.36 v1(35.79,97.36) U10.3
  BOTTOM w0.305: v1(35.66,94.36) 35.79,94.49 v1(35.79,97.36)
N19839460: length 2.7
  BOTTOM w0.305: R29.1 R28.2 35.29,79.79 U15.1
N19839464: length 8.6
  BOTTOM w0.305: U15.7 35.06,78.54 R28.1 35,76.2 C195.1 34.43,74.71 L2.2
N19839484: length 27.3
  BOTTOM w0.305: 36.92,74.42 36.92,74.74 U15.6 ; 36.92,74.42 L4.1 ; 36.92,74.42 36.6,74.42 36.6,69.9 v1(36.91,72.64) L4.1 ; L4.1 36.93,72.2 37.04,73.87 36.95,74.7 U15.6 ; L4.1 37.24,72.5 U15.6
  vias: v1(36.87,73.66) v1(36.92,71.68) v1(36.92,70.74) v2(37.16,77.65) v2(37.08,76.96) v2(37.24,79.02) v2(37.24,78.34)
N19839486: length 4.3
  BOTTOM w0.305: U15.4 37.99,80.53 C196.1 40.03,81.2 R33.2 R37.1
N19839498: length 6
  BOTTOM w0.305: R33.1 40.06,74.8 v1(40.89,73.96)
  vias: v1(40.87,75.08) v1(40.92,72.75) v1(41.99,75.08) v1(42.01,73.96) v1(42.04,72.75) v1(43.21,75.08) v1(43.23,73.96) v1(43.26,72.75) v1(44.35,75.08) v1(44.37,73.96) v1(44.4,72.75)
N19839502: length 4.1
  BOTTOM w0.305: R37.2 R32.1 37.08,82.3 C196.2 37.49,80.8 U15.3
N19884960: length 1.6
  TOP w0.508: v3(99.29,94.13) 99.72,93.7 ; 99.72,93.7 R143.1 ; 99.72,93.7 R144.2
N19885012: length 1.1
  TOP w0.508: T7.4 C274.1
N19885116: length 1.2
  TOP w0.508: R145.2 101.61,92.74 101.43,92.74 C276.2
N19885138: length 1.2
  TOP w0.508: C276.1 100.69,92.04 100.69,91.86 R146.1
N19885156: length 4.5
  TOP w0.508: T6.5 T6.2 94.29,99.15 v3(93.24,100.2)
N19885198: length 4.5
  TOP w0.508: T7.2 T7.5 v3(96.34,97.1)
N19885294: length 1.1
  TOP w0.508: T9.4 C203.1
N19885373: length 1.6
  TOP w0.508: v3(124.36,94.23) 123.92,93.79 ; 123.92,93.79 R156.1 ; 123.92,93.79 R155.2
N19885375: length 4.6
  TOP w0.508: T8.2 131.49,101.41 131.49,101.4 v3(130.43,100.33)
N19885421: length 4.6
  TOP w0.508: v3(127.3,97.21) 126.24,96.15 T9.5 T9.2
N19885585: length 1.2
  TOP w0.508: C207.2 122.99,92.18 122.99,92 R157.2
N19885597: length 1.2
  TOP w0.508: R158.1 122.13,92.94 122.31,92.94 C207.1
N19895674: length 4.5
  TOP w0.241: R186.1 117.4,72.9 R183.1 117.4,74.09 R182.2 117.24,74.25 117.24,75.17 116.08,76.33 116.08,76.7 U1.72
N19895681: length 4.5
  TOP w0.241: U1.71 115.7,76.7 115.7,76.17 116.86,75.01 116.86,74.21 R182.1 116.74,74.09 R184.2 116.74,72.9 R185.1
N19922962: length 1.1
  TOP w0.508: C141.1 T2.4
N19926392: length 3
  TOP w0.508: T1.5 v3(87.08,83.65) T1.2
N19927040: length 3
  TOP w0.508: T2.2 v3(91.4,83.65) T2.5
N19928466: length 1.1
  TOP w0.508: T9.6 127.31,95.06 C202.1
N19936516: length 1.1
  TOP w0.508: C140.1 92.97,85.18 T2.6
N19989779: length 1.1
  TOP w0.508: C275.1 98.49,97.12 T7.6
N20022529:
  vias: v1(36.73,94.36)
N20035911:
  vias: v1(34.65,85.83)
N20038291: length 1.6
  TOP w0.356: U9.15 49.2,78.74 C265.1
N20038313: length 3
  TOP w0.356: U9.11 49.25,81.34 R166.2 R167.1
N20038327:
  vias: v1(52.6,75.74)
N20038329: length 1.9
  TOP w0.305: v1(51.56,75.77) 51.56,76.48 52.07,76.98 U9.16
N20038355: length 6.8
  TOP w0.305: C115.1 56.52,78.74 U9.1 ; U9.18 53.37,76.73 R129.1 53.82,74.75 R64.1
  vias: v1(55.65,77.65) v1(55.68,76.61) v1(55.7,75.59) v1(56.74,77.65) v1(56.77,76.61) v1(56.79,75.59) v1(57.89,77.65) v1(57.91,76.61) v1(57.94,75.59) v1(58.9,77.62) v1(58.93,76.58) v1(58.95,75.56)
N20039194: length 3.7
  TOP w0.305: C286.1 36.59,67.94 36.59,65.56 36.81,65.35 U16.6
N20039222: length 1
  BOTTOM w0.305: v2(37.32,66) 37.3,66.01 R178.1
  vias: v2(37.82,66)
N20039339:
  vias: v1(43.94,64.62) v1(43.97,63.75) v1(43.94,62.89) v1(43.94,61.98) v1(44.93,64.62) v1(44.96,63.75) v1(44.91,62.87) v1(44.91,61.95)
N20039347: length 5.7
  TOP w0.356: v1(42.32,65.71) 41.96,65.35 U16.3
  BOTTOM w0.356: v1(42.27,62) 42.32,62.05 v1(42.32,65.71)
N20052215:
  vias: v1(109.73,103.12)
N20058798: length 1.8
  TOP w0.356: v1(51.77,84.33) 52.07,84.03 U9.10
N20074843: length 3.6
  TOP w0.305: C114.1 30.84,109.83 30.84,107.56 31.14,107.26 U11.6
N20074851: length 1.5
  BOTTOM w0.305: R189.1 v2(31.45,107.92) R188.2 v2(31.95,107.92)
N20074920: length 5.1
  TOP w0.305: C106.2 v1(35.63,107.26) U11.3
  BOTTOM w0.305: v1(35.63,107.26) 35.63,104.57 v1(35.31,104.24)
N20074982:
  vias: v1(36.32,104.24)
N195971120: length 1.1
  TOP w0.152: C66.2 R65.1
N195974181: length 1.3
  TOP w0.254: C65.2 R66.1

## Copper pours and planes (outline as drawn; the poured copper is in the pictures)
5.0V_IN on BOTTOM (solid shape): 21.96,58.45 18.15,58.45 18.15,62.97 21.96,62.97
5.0V_IN on TOP: 4.93,55.8 4.93,68.07 10.92,68.07 10.92,65.91 21.72,65.91 21.72,55.8
5.0V_IN on BOTTOM: 4.94,55.82 4.94,68.02 10.92,68.02 10.92,65.91 21.72,65.91 21.72,55.82
5VIN on TOP: 30.61,75.69 30.61,69.98 32.64,69.98 32.64,75.69
5VIN on TOP: 22.73,59.69 22.73,66.29 28.83,66.29 28.83,59.69
5VIN on TOP: 6.12,70.59 6.12,73.76 6.32,73.76 6.32,74.32 7.59,74.32 7.59,74.27 7.92,74.27 8.05,74.4 8.31,74.4 8.31,73.51 9.07,73.51 9.07,70.59
5VIN on TOP, BOTTOM: 10.39,90.91 9.45,90.91 9.45,91.29 6.53,91.29 6.53,94.31 3.78,94.31 3.78,84.79 5.69,82.88 10.39,82.88
5VIN on BOTTOM: 20.57,41.66 20.57,38.35 23.88,38.35 23.88,41.66
5VIN on BOTTOM: 22.73,59.69 22.73,66.29 28.35,66.29 28.35,75.72 32.82,75.72 32.82,59.69
5VIN on L3-PWR1: 2.67,34.8 2.67,95.12 13.46,95.12 13.46,76.07 18.54,76.07 18.54,65.28 26.8,65.28 29.34,62.74 29.34,34.8
+2.5V on TOP: 31.88,64.9 31.88,61.87 37.97,61.87 37.97,64.9
+2.5V on TOP: 25.5,98.22 23.62,98.22 22.28,99.57 15.37,99.57 15.37,104.52 15.24,104.65 8.61,104.65 8.61,107.82 19.79,107.82 25.5,102.11
+2.5V on TOP: 53.24,84.89 53.24,82.17 55.09,82.17 55.42,81.84 55.42,81.15 58.12,81.15 58.12,84 56.95,85.17 53.52,85.17
+2.5V on TOP: 28.42,96.98 28.42,93.95 32.31,93.95 32.31,96.98
+2.5V on TOP: 26.52,88.57 26.52,85.55 30.4,85.55 30.4,88.57
+2.5V on TOP, BOTTOM: 32.15,106.8 29.12,106.8 29.12,102.91 32.15,102.91
+2.5V on BOTTOM: 25.45,98.27 23.62,98.27 22.33,99.57 15.37,99.57 15.37,104.52 15.24,104.65 8.61,104.65 8.61,107.82 19.74,107.82 25.45,102.11
+2.5V on L3-PWR1: 14.73,77.34 14.73,98.93 7.75,98.93 7.75,108.46 41.4,108.46 41.4,89.41 56.01,89.41 58.55,86.87 58.55,80.52 47.12,80.52 47.12,77.34
+2.5V on L6-PWR2: 24.26,91.31 24.26,70.99 33.78,61.47 38.23,61.47 38.23,91.31
+3.3VCLK on TOP: 73.28,52.37 73.28,50.09 75.77,50.09 75.77,52.37
+3.3VCLK on TOP: 26.09,71.62 26.09,78.13 20.19,78.13 20.19,70.84 20.42,70.64 25.37,70.64
+3.3VCLK on BOTTOM: 95.78,66.27 95.78,65 98.45,65 98.45,66.27
+3.3VCLK on BOTTOM: 104.75,52.6 104.75,48.97 106.35,48.97 106.35,52.6
+3.3VCLK on BOTTOM: 101.47,56.72 101.47,54.76 104.65,54.76 104.65,56.72
+3.3VCLK on BOTTOM: 73.28,64.01 73.28,56.39 76.2,56.39 76.2,64.01
+3.3VCLK on L3-PWR1: 30.61,34.8 30.61,65.91 20.45,65.91 20.45,76.07 42.67,76.07 51.56,67.18 121.41,67.18 121.41,34.8 ; 1 cut-out
AVDD1.9V on TOP: 44.48,103.07 44.48,108.76 49.17,108.76 49.17,103.07
AVDD1.9V on BOTTOM: 44.48,103.1 44.48,108.79 49.17,108.79 49.17,103.1
AVDD1.9V on L6-PWR2: 49.66,81.53 49.66,90.68 43.94,90.68 43.94,111.63 64.26,111.63 64.26,93.85 123.9,93.85 123.9,79.25 119.1,79.25 119.1,81.79 107.75,81.79 107.49,81.53
AVDD1.15V on TOP, BOTTOM: 42.82,97.94 42.82,92.58 48.59,92.58 48.59,97.94
AVDD1.15V on L3-PWR1: 56.01,90.68 42.67,90.68 42.67,98.3 64.26,98.3 64.26,95.76 66.17,93.85 119.51,93.85 119.51,79.88 66.8,79.88
GND on TOP (solid shape): 31.28,89.35 31.65,89.35 31.65,90.38 31.93,90.38 31.93,89.35 32.22,89.35 32.22,87.6 31.93,87.6 31.93,86.58 31.65,86.58 31.65,87.6 31.28,87.6 31.28,86.58 31,86.58 31,87.6 30.72,87.6 30.72,89.35 31,89.35 31,90.38 31.28,90.38
